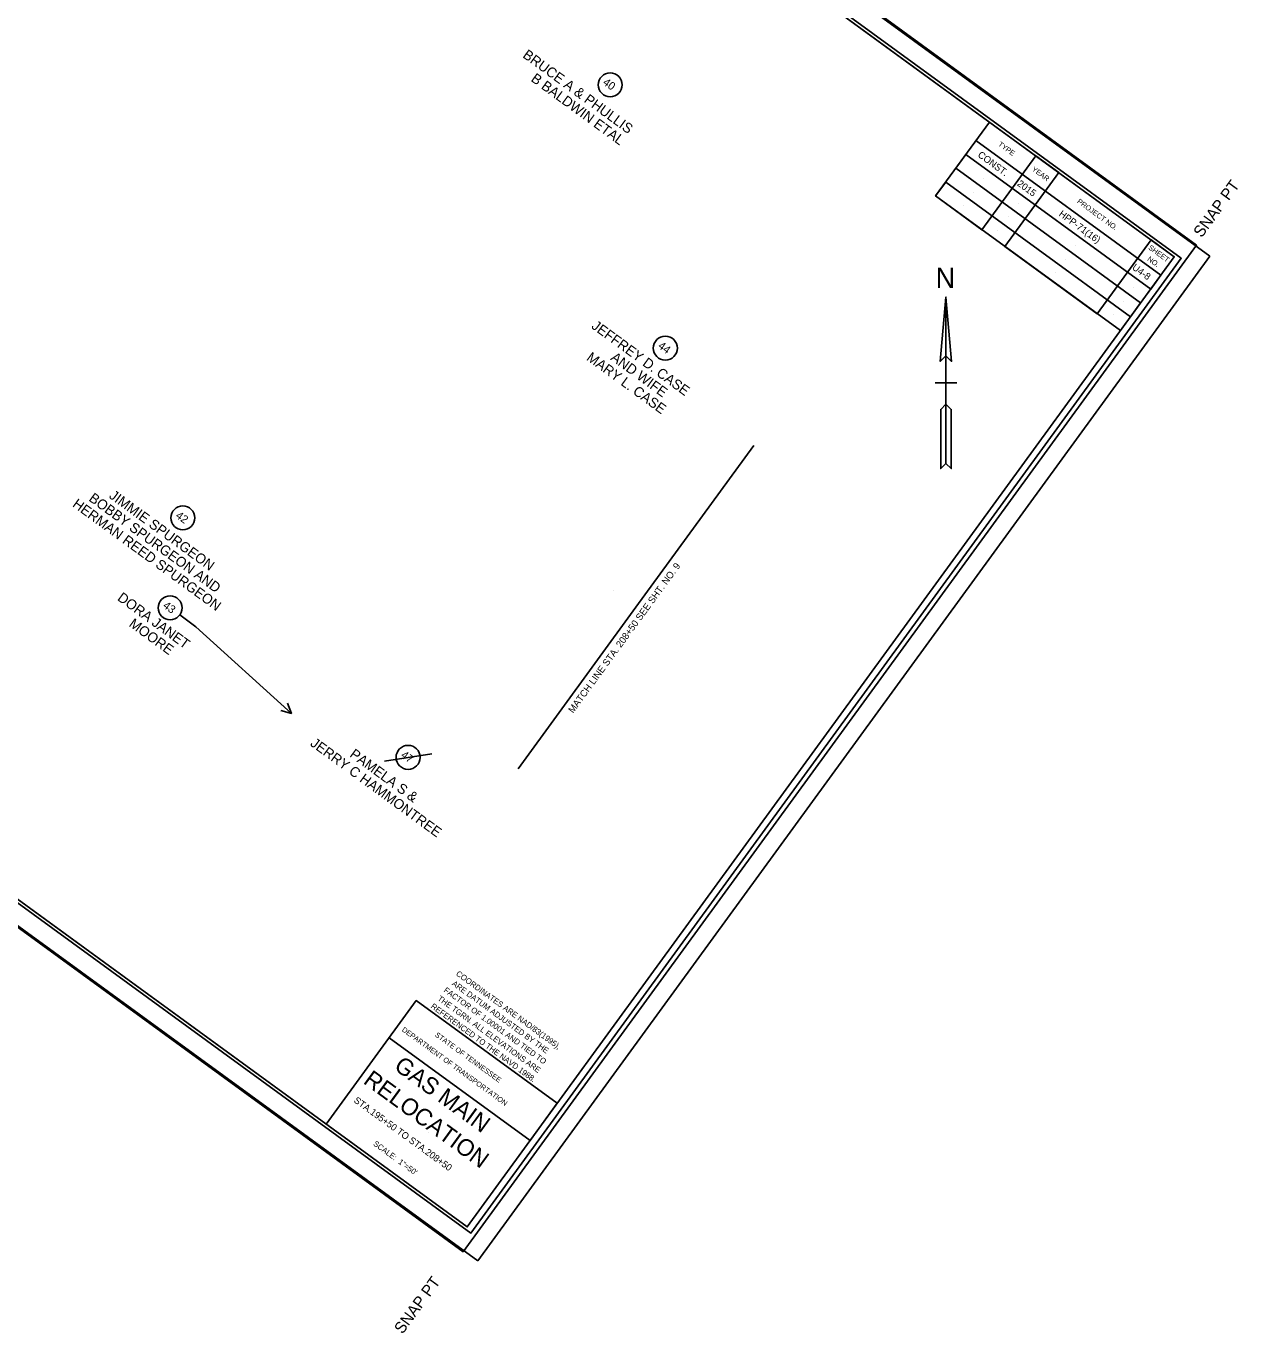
# Model space of a CAD drawing. Extents: x 2630958 to 2633078, y 566931 to 568943.
# Drawn here: x 2632018 to 2633078, y 566931 to 568075 of the extents above; entities that cross this region are included whole.
import ezdxf

# ---------------------------------------------------------------- set-up
doc = ezdxf.new("R2010")
doc.units = 0
for name, color, linetype in [('DESIGN - CENTERLINE - Proposed Text', 7, 'Continuous'), ('DESIGN - SCRATCH - User 1', 7, 'Continuous'), ('DESIGN - SHEET - Corner Text', 7, 'Continuous'), ('DESIGN - SHEET - Light Grid', 7, 'Continuous'), ('DESIGN - SHEET - Linework', 7, 'Continuous'), ('DESIGN - SHEET - Plot Shape', 7, 'Continuous'), ('SURVEY - PROPERTY - Owners', 7, 'Continuous'), ('SURVEY - PROPERTY - Tract Numbers', 7, 'Continuous')]:
    doc.layers.add(name, color=color, linetype=linetype)

msp = doc.modelspace()

# ---------------------------------------------------------------- linework, layer by layer
at = {"layer": 'DESIGN - CENTERLINE - Proposed Text'}
for p, q in [((2632822.3, 567763.1), (2632812.9, 567763.1)), ((2632831.8, 567763.1), (2632822.3, 567763.1))]:
    msp.add_line(p, q, dxfattribs=at)
for points in [[(2632822.3, 567838.1), (2632817.4, 567781.8), (2632822.3, 567786.7), (2632827.2, 567781.8), (2632822.3, 567838.1), (2632822.3, 567692.6), (2632826.9, 567688.1), (2632826.9, 567739.8), (2632822.3, 567744.4), (2632817.8, 567739.8), (2632817.8, 567688.1), (2632822.3, 567692.6)], [(2632448.1, 567425.5), (2632551.2, 567566.9), (2632654.3, 567708.4)]]:
    msp.add_lwpolyline(points, dxfattribs=at)
for points in [[(2632822.3, 567786.7), (2632827.2, 567781.8), (2632822.3, 567838.1)], [(2632817.8, 567688.1), (2632822.3, 567692.6), (2632822.3, 567744.4), (2632817.8, 567739.8)]]:
    msp.add_lwpolyline(points, close=True, dxfattribs=at)
at = {"layer": 'DESIGN - SCRATCH - User 1'}
for p, q in [((2632864.4, 567954.3), (2632864.4, 567954.3)), ((2632855.6, 567942.1), (2632855.6, 567942.1)), ((2632846.7, 567930), (2632846.7, 567930)), ((2632894.3, 567932.5), (2632894.3, 567932.5)), ((2632837.9, 567917.9), (2632837.9, 567917.9)), ((2632885.5, 567920.4), (2632885.5, 567920.4)), ((2632876.6, 567908.2), (2632876.6, 567908.2)), ((2632867.8, 567896.1), (2632867.8, 567896.1)), ((2632944.8, 567895.7), (2632944.8, 567895.7)), ((2632936, 567883.5), (2632936, 567883.5)), ((2632927.1, 567871.4), (2632927.1, 567871.4)), ((2632918.3, 567859.3), (2632918.3, 567859.3)), ((2632995.3, 567858.9), (2632995.3, 567858.9)), ((2632986.5, 567846.7), (2632986.5, 567846.7)), ((2632977.7, 567834.6), (2632977.7, 567834.6)), ((2632968.8, 567822.5), (2632968.8, 567822.5)), ((2632531.6, 567581.2), (2632531.6, 567581.2)), ((2632369.6, 567107.6), (2632369.6, 567107.6))]:
    msp.add_line(p, q, dxfattribs=at)
at = {"layer": 'DESIGN - SHEET - Light Grid'}
msp.add_lwpolyline([(2631061.2, 568000), (2632406.8, 567019.4), (2633028.1, 567872.1), (2631682.5, 568852.7)], close=True, dxfattribs=at)
at = {"layer": 'DESIGN - SHEET - Linework'}
for p, q in [((2631598.5, 568933.9), (2633053.2, 567873.8)), ((2630958.1, 568055.1), (2632412.8, 566995)), ((2633053.2, 567873.8), (2632412.8, 566995))]:
    msp.add_line(p, q, dxfattribs=at)
for points in [[(2631749.8, 568800.5), (2631131.4, 567952), (2632403.6, 567024.8), (2633022, 567873.4), (2631749.8, 568800.5)], [(2632860.4, 567991.2), (2632813.3, 567926.6), (2632974.9, 567808.8), (2633022, 567873.4), (2633001.8, 567888.2), (2632954.7, 567823.5), (2632873.9, 567882.4), (2632921, 567947), (2632900.8, 567961.8), (2632853.7, 567897.1), (2632813.3, 567926.6), (2632822.1, 567938.7), (2632983.7, 567820.9), (2632992.6, 567833), (2632830.9, 567950.8), (2632839.8, 567962.9), (2633001.4, 567845.1), (2633010.2, 567857.3), (2632848.6, 567975.1)], [(2632280.4, 567114.7), (2632359.1, 567222.7), (2632482.3, 567132.9), (2632458.8, 567100.5), (2632335.5, 567190.3)]]:
    msp.add_lwpolyline(points, dxfattribs=at)
at = {"layer": 'DESIGN - SHEET - Plot Shape'}
for points in [[(2631667.7, 568884.8), (2633041.6, 567883.5), (2632400, 567003.1), (2631026.1, 568004.3)], [(2631681.1, 568850.6), (2633022, 567873.4), (2632403.6, 567024.8), (2631062.7, 568002)]]:
    msp.add_lwpolyline(points, close=True, dxfattribs=at)
at = {"layer": 'SURVEY - PROPERTY - Tract Numbers'}
msp.add_line((2632331.2, 567432.2), (2632372.6, 567438.7), dxfattribs=at)
for points in [[(2632166.4, 567549.8), (2632152.3, 567560.1)], [(2632249.9, 567473.9), (2632166.4, 567549.8)], [(2632246.4, 567483), (2632249.9, 567473.9), (2632240.5, 567476.5)]]:
    msp.add_lwpolyline(points, dxfattribs=at)
for centre in [(2632528.7, 568023.8), (2632576.9, 567793.5), (2632154.9, 567645), (2632143.8, 567566.3), (2632351.9, 567435.5)]:
    msp.add_circle(centre, 10.5, dxfattribs=at)

# ---------------------------------------------------------------- texts
at = {"layer": 'DESIGN - CENTERLINE - Proposed Text'}
msp.add_text('N', height=17.7, dxfattribs=at).set_placement((2632813.3, 567846.1))
msp.add_text('MATCH LINE STA. 208+50 SEE SHT. NO. 9', height=6, rotation=53.918, dxfattribs=at).set_placement((2632496.3, 567473.7))
at = {"layer": 'DESIGN - SHEET - Corner Text'}
for s, height, rotation, p in [('TYPE', 4.5, 323.918, (2632867.5, 567970.9)), ('CONST.', 6, 323.918, (2632849.6, 567961.4)), ('YEAR', 4.5, 323.918, (2632897.1, 567949.1)), ('2015', 6, 323.918, (2632884.1, 567936.2)), ('  SNAP PT', 10, 53.918, (2633041.6, 567883.5)), ('PROJECT NO.', 4.5, 323.918, (2632936.6, 567920.9)), ('HPP-71(16)', 6, 323.918, (2632920.5, 567909.7)), ('SHEET', 4.5, 323.918, (2632998.9, 567880.5)), ('NO.', 4.5, 323.918, (2632998, 567870.5)), ('U4-8', 6, 323.918, (2632984.6, 567862.9)), ('COORDINATES ARE NAD/83(1995),', 5, 323.918, (2632393.3, 567245.2)), ('FACTOR OF 1.00001 AND TIED TO', 5, 323.918, (2632382.6, 567230.8)), ('ARE DATUM ADJUSTED BY THE', 5, 323.918, (2632389.8, 567236.6)), ('REFERENCED TO THE NAVD 1988.', 5, 323.918, (2632371.3, 567216.7)), ('THE TGRN. ALL ELEVATIONS ARE', 5, 323.918, (2632377.2, 567223.5)), ('DEPARTMENT OF TRANSPORTATION', 4.5, 323.918, (2632346, 567196.4)), ('STATE OF TENNESSEE', 4.5, 323.918, (2632375, 567191.8)), ('GAS MAIN', 14.76, 323.918, (2632338.7, 567163.2)), ('RELOCATION', 14.76, 323.918, (2632311.9, 567150.9)), ('STA.195+50 TO STA.208+50', 5.906, 323.918, (2632303.9, 567134.3)), ('SCALE:  1"=50\'', 4.921, 323.918, (2632321, 567096.5)), ('SNAP PT  ', 10, 53.918, (2632347, 566930.4))]:
    msp.add_text(s, height=height, rotation=rotation, dxfattribs=at).set_placement(p)
at = {"layer": 'SURVEY - PROPERTY - Owners'}
for s, p in [('BRUCE A & PHULLIS ', (2632451.5, 568048.3)), ('B BALDWIN ETAL', (2632458.7, 568027.6)), ('JEFFREY D. CASE', (2632511.6, 567811.4)), ('MARY L. CASE', (2632507.3, 567783.6)), ('AND WIFE', (2632528.4, 567783.7)), ('BOBBY SPURGEON AND', (2632072, 567660.5)), ('JIMMIE SPURGEON', (2632089.7, 567663)), ('HERMAN REED SPURGEON', (2632057.7, 567655.4)), ('DORA JANET', (2632097, 567573.5)), ('MOORE', (2632107.1, 567550.7)), ('JERRY C HAMMONTREE', (2632265.7, 567446.3)), ('PAMELA S &', (2632300.2, 567436.6))]:
    msp.add_text(s, height=8.75, rotation=323.918, dxfattribs=at).set_placement(p)
at = {"layer": 'SURVEY - PROPERTY - Tract Numbers'}
for s, p in [('40', (2632521.6, 568024.7)), ('44', (2632569.9, 567794.2)), ('42', (2632148, 567645.7)), ('43', (2632136.9, 567567)), ('47', (2632345, 567436.2))]:
    msp.add_text(s, height=7, rotation=323.918, dxfattribs=at).set_placement(p)

doc.saveas('drawing.dxf')
